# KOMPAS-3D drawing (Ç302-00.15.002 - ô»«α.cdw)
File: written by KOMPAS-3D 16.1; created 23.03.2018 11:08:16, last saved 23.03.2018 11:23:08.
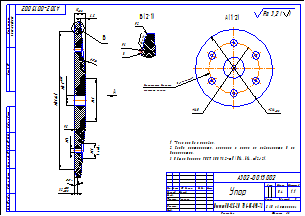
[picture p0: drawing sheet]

Sheet 1: A3, landscape

Title block, sheet 1: name: Упор; designation: А302-00.15.002; material: Полиамид П-12Б-20  ТУ 6-05-898-73; mass: 0,4; scale: 1:1; sheets: 1; organisation: ЗАО «Астерион»; sheet format: A3; stored path: \\192.168.87.28\Konstructor_doc\Мембранные насосы\Мембранный электропривод\А302-00.00.000 - ASTRA-302 (МЭ200)\Чертежи\А302-00.15.002 - Упор.cdw; drawn by: Милов; technical control: Лучихин

Views: Вид 1, Местный разрез 1, Спереди, Вид по стрелке 2, Выносной элемент 3, Выносной элемент Б, Выносной элемент
Referenced files in Z:\Мембранные насосы\Мембранный электропривод\А302-00.00.000 - ASTRA-302 (МЭ200)\3Д\: А302-00.15.002 - Упор.m3d
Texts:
  допускается диаметр
  очертить резцом
  для разметки
  Ra 0,80
  *Размеры для справок.
  Следы инструмента, царапины и риски на поверхности  В  не
  допускаются.
  Общие допуски ГОСТ 30893.2-mK (H14, h14,  t2/2).
  Ra 3,2
  Ra 3,2 ( )
Dimensions and other numbers on the sheet: 13,5; 60; 190±0,1; 3,2; 5,6; 20; 6 отв.; 9,5; 15; 4 50'; 6,5; 214; 140; 6; 2; 1:1; 1; 0,4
